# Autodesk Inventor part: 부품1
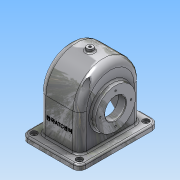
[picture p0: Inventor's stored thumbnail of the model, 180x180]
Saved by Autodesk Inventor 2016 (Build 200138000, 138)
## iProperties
Created: 2018-08
Part Number: 부품1
Material: 알루미늄 6061
Document SubType Name: Modeling
Designer: Administrator
Density: 2.7 g/cm^3
Appearance: 알루미늄 - 평지
Mass: 1091.75 g
Surface Area: 1182.51 cm^2
Volume: 404.352 cm^3
Author: Administrator
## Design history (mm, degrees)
sketch "스케치2"
  geometry: L1 (-43, -75)-(43, -75); L2 (55, -63)-(55, 63); L3 (43, 75)-(-43, 75); L4 (-55, 63)-(-55, -63); L5 (-55, -75)-(55, 75); L6 (55, -75)-(-55, 75); A1 r 12 centre (-43, 63) between (-43, 75) and (-55, 63); A2 r 12 centre (-43, -63) between (-55, -63) and (-43, -75); A3 r 12 centre (43, -63) between (43, -75) and (55, -63); A4 r 12 centre (43, 63) between (55, 63) and (43, 75); 1 further point
  constraints: 12 end point, 8 point on circle, 8 point on line, 8 tangent, 4 centre point, 3 equal radius, 2 midpoint, 2 parallel, 1 horizontal, 1 perpendicular
  dimensions: "d0" = 110 distance of L6.end L5.end; "d1" = 150 distance of L5.end L6.start; "d2" = 12 radius of A1
extrude "돌출1" new body sketch "스케치2" distance "d3" = 10; taper "d4" = 0 deg
sketch "스케치3" dims "d6" = 58
  geometry: L1 (63, 10)-(-63, 10) reference; L2 (58, 10)-(-58, 10); L3 (-58, 10)-(-58, 78); L4 (-58, 78)-(58, 78); L5 (58, 78)-(58, 10); L6 (-63, 0)-(63, 0) reference; L7 (0, 0)-(0, 175.112); 1 further point
  constraints: 10 end point, 2 parallel, 1 horizontal, 1 horizontal alignment, 1 midpoint, 1 perpendicular, 1 point on line, 1 vertical, 3 other
  dimensions: "d5" = 78 distance between parallel lines of L6 L4
extrude "돌출2" join sketch "스케치3" stored distance "d7" = 77; taper "d8" = 0 deg
fillet "모깎기1" dims "d9" = 13
sketch "스케치4"
  geometry: L1 (63, 0)-(-63, 0) reference; L2 (52, 78)-(-52, 78); L3 (-52, 78)-(-52, 0); L4 (-52, 0)-(52, 0); L5 (52, 0)-(52, 78); A1 r 58 centre (0, 78) between (58, 78) and (-58, 78) reference; A2 r 52 centre (0, 78) between (52, 78) and (-52, 78); 1 further point
  constraints: 8 end point, 2 parallel, 2 point on circle, 1 centre point, 1 horizontal, 1 midpoint, 1 perpendicular, 1 point on line
  dimensions: "d10" = 6 radial gap between concentric circles of A1 A2
extrude "돌출3" cut sketch "스케치4" stored distance "d11" = 67; taper "d12" = 0 deg
sketch "스케치5"
  geometry: L1 (61.566, 65)-(-56.824, 65); L2 (-33.5, 0)-(33.5, 0) reference; L3 (43.5, 85)-(43.5, 103); L4 (43.5, 103)-(31.418, 103); L5 (31.418, 103)-(19.5, 93); L6 (19.5, 93)-(19.5, 85); L7 (19.5, 85)-(43.5, 85); L8 (33.5, 78)-(33.5, 130) reference; L9 (38.5, 123)-(38.5, 78) reference; 1 further point
  constraints: 12 end point, 2 perpendicular, 1 horizontal, 1 parallel, 1 vertical
  dimensions: "d13" = 65 distance between parallel lines of L2 L1; "d14" = 40 diameter of L7 L1; "d15" = 76 diameter of L4 L1; "d16" = 50 deg angle of L6 L5; "d17" = 24 distance of L6.end L3.start; "d18" = 5 distance between parallel lines of L3 L9; "d121" = 56 diameter of L5.end L1
revolve "회전1" sketch "스케치5" stored, may be unused: angle "d19" = 90 deg
sketch "스케치6"
  geometry: L1 (0, -63)-(0, 63) reference; C1 r 38 at (-65, 0); 2 further points
  constraints: 1 centre point, 1 horizontal alignment, 1 midpoint
  dimensions: "d20" = 76 diameter of C1; "d21" = 65 distance from line of L1 C1.centre
extrude "돌출4" join sketch "스케치6" distance "d22" = 10; taper "d23" = 0 deg
hole "구멍1" diameter "d26" = 40; stored, may be unused: countersink angle "d30" = 90 deg, drill point angle "d32" = 118 deg; dims "d24" = 10, "d25" = 10, "d27" = 6, "d28" = 4, "d29" = 2, "d31" = 8
node "작업 평면1"
sketch "스케치8"
  geometry: C1 r 6 at (0, 0); 1 further point
  constraints: 1 centre point, 1 coincident
  dimensions: "d34" = 12 diameter of C1
extrude "돌출5" join sketch "스케치8" stored distance "d35" = 10; taper "d36" = 5 deg
hole "구멍2" diameter "d39" = 4.459; stored, may be unused: countersink angle "d43" = 90 deg, drill point angle "d45" = 118 deg; dims "d40" = 20, "d41" = 4, "d42" = 2, "d44" = 12.8, "d108" = 10, "d109" = 10
hole "구멍3" diameter "d48" = 5; stored, may be unused: countersink angle "d52" = 90 deg, drill point angle "d54" = 118 deg; dims "d46" = 10, "d47" = 10, "d49" = 10, "d50" = 12, "d51" = 4, "d53" = 12.8
hole "구멍4" diameter "d57" = 5; stored, may be unused: countersink angle "d61" = 90 deg, drill point angle "d63" = 118 deg; dims "d55" = 10, "d56" = 10, "d58" = 10, "d59" = 12, "d60" = 4, "d62" = 12.8
hole "구멍5" diameter "d66" = 5; stored, may be unused: countersink angle "d70" = 90 deg, drill point angle "d72" = 118 deg; dims "d64" = 10, "d65" = 10, "d67" = 10, "d68" = 12, "d69" = 4, "d71" = 12.8
hole "구멍6" diameter "d75" = 5; stored, may be unused: countersink angle "d79" = 90 deg, drill point angle "d81" = 118 deg; dims "d73" = 10, "d74" = 10, "d76" = 10, "d77" = 12, "d78" = 4, "d80" = 12.8
sketch "스케치9"
  geometry: L1 (65, -63)-(65, 63) reference; 3 further points
  constraints: 1 horizontal alignment, 1 midpoint
  dimensions: "d82" = 94 distance from line of L1 point (-29, 0)
hole "구멍7" sketch "스케치9" at (-29, 0) diameter "d83" = 3.242; stored, may be unused: countersink angle "d87" = 90 deg, drill point angle "d89" = 118 deg; dims "d84" = 8, "d85" = 12, "d86" = 4, "d88" = 10
chamfer "모따기1" distance "d93" = 1; stored, may be unused: second distance "d94" = 2, angle "d95" = 45 deg
chamfer "모따기2" distance "d96" = 1; stored, may be unused: second distance "d97" = 2, angle "d98" = 45 deg
fillet "모깎기2" dims "d99" = 8
fillet "모깎기3" dims "d100" = 3
fillet "모깎기4" dims "d101" = 3
fillet "모깎기5" dims "d102" = 3
sketch "스케치10"
  geometry: L1 (-17.5, -78)-(68.5, -78) reference; L2 (-13, 0)-(-13, -65) reference; 2 further points
  constraints: 1 other
  dimensions: "d103" = 40 distance from line of L1 point (25.5, -38); "d104" = 38.5 distance from line of L2 point (25.5, -38)
feature "엠보싱1" sketch "스케치10" dims "d0" = 110, "d1" = 150, "d2" = 12, "d5" = 78, "d6" = 58, "d105" = 0.5, "d106" = 0
sketch "스케치11"
  geometry: L1 (-65, 63)-(-65, -63) reference; 3 further points
  constraints: 1 horizontal alignment, 1 midpoint
  dimensions: "d110" = 94 distance from line of L1 point (29, 0)
hole "구멍8" sketch "스케치11" at (29, 0) diameter "d111" = 3.242; stored, may be unused: countersink angle "d115" = 90 deg, drill point angle "d117" = 118 deg; dims "d112" = 8, "d113" = 12, "d114" = 4, "d116" = 10
fillet "모깎기7" dims "d122" = 3
node "솔리드1"
pattern_circular "원형 패턴1" dims angle "d91" = 360 deg
pattern_circular "원형 패턴2" dims angle "d119" = 360 deg
other parameters: "d33" = 142
